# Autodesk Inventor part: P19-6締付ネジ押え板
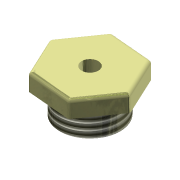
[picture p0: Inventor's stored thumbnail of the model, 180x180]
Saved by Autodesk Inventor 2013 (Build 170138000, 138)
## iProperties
Shininess: 64.0
Length Units: 11269
Angle Units: 11279
Time Units: 11290
Mass Units: 11284
Length Display Precision: 2
Angle Display Precision: 1
Created: 2002-10
Part Number: P19-6締付ネジ押え板
Document SubType Name: ﾓﾃﾞﾘﾝｸﾞ
Designer: 株式会社富士システム
Stock Number: P19-6締付ネジ押え板
Density: 1 g/cm^3
Material: 一般
Density: 0.0
Volumn: 0.0
Area: 0.0
PropertySet Name: Model Information
Control State: 0
Master: False
Checked Out: False
Author: 株式会社富士システム
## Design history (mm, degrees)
sketch "ｽｹｯﾁ1"
  geometry: C1 r 18 at (16.993, -14.869)
  constraints: 1 centre point
  dimensions: "d0" = 36 diameter of C1
extrude "押し出し1" new body sketch "ｽｹｯﾁ1" distance "d1" = 15; taper "d2" = 0 deg
sketch "ｽｹｯﾁ2"
  geometry: L1 (11.232, -24.066)-(-15.225, -21.76); L2 (-15.225, -21.76)-(-26.458, 2.305); L3 (-26.458, 2.305)-(-11.232, 24.066); L4 (-11.232, 24.066)-(15.225, 21.76); L5 (15.225, 21.76)-(26.458, -2.305); L6 (26.458, -2.305)-(11.232, -24.066); C1 r 18 at (0, 0) reference; 1 further point
  constraints: 12 end point, 1 coincident, 11 other
  dimensions: "d4" = 23 distance from line of L4 L5.end
extrude "押し出し2" join sketch "ｽｹｯﾁ2" distance "d5" = 10; taper "d6" = 0 deg
feature "ねじ1" dims "d7" = 10, "d8" = 0
sketch "ｽｹｯﾁ3"
  geometry: C1 r 18 at (0, 0) reference; C2 r 5 at (0, 0)
  constraints: 1 centre point, 1 coincident
  dimensions: "d9" = 10 diameter of C2
extrude "押し出し3" cut sketch "ｽｹｯﾁ3" stored distance "d10" = 10; taper "d11" = 0 deg
fillet "ﾌｨﾚｯﾄ1" dims "d12" = 2
node "ソリッド1"
node "ソリッド ボディ"
node "サーフェス ボディ"
